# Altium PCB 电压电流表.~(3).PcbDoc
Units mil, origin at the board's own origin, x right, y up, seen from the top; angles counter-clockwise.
Board outline 2295 x 2570 mil, 2 copper layers (Top Layer, Bottom Layer); 25 components, 47 nets, 141 pads, 0 vias.
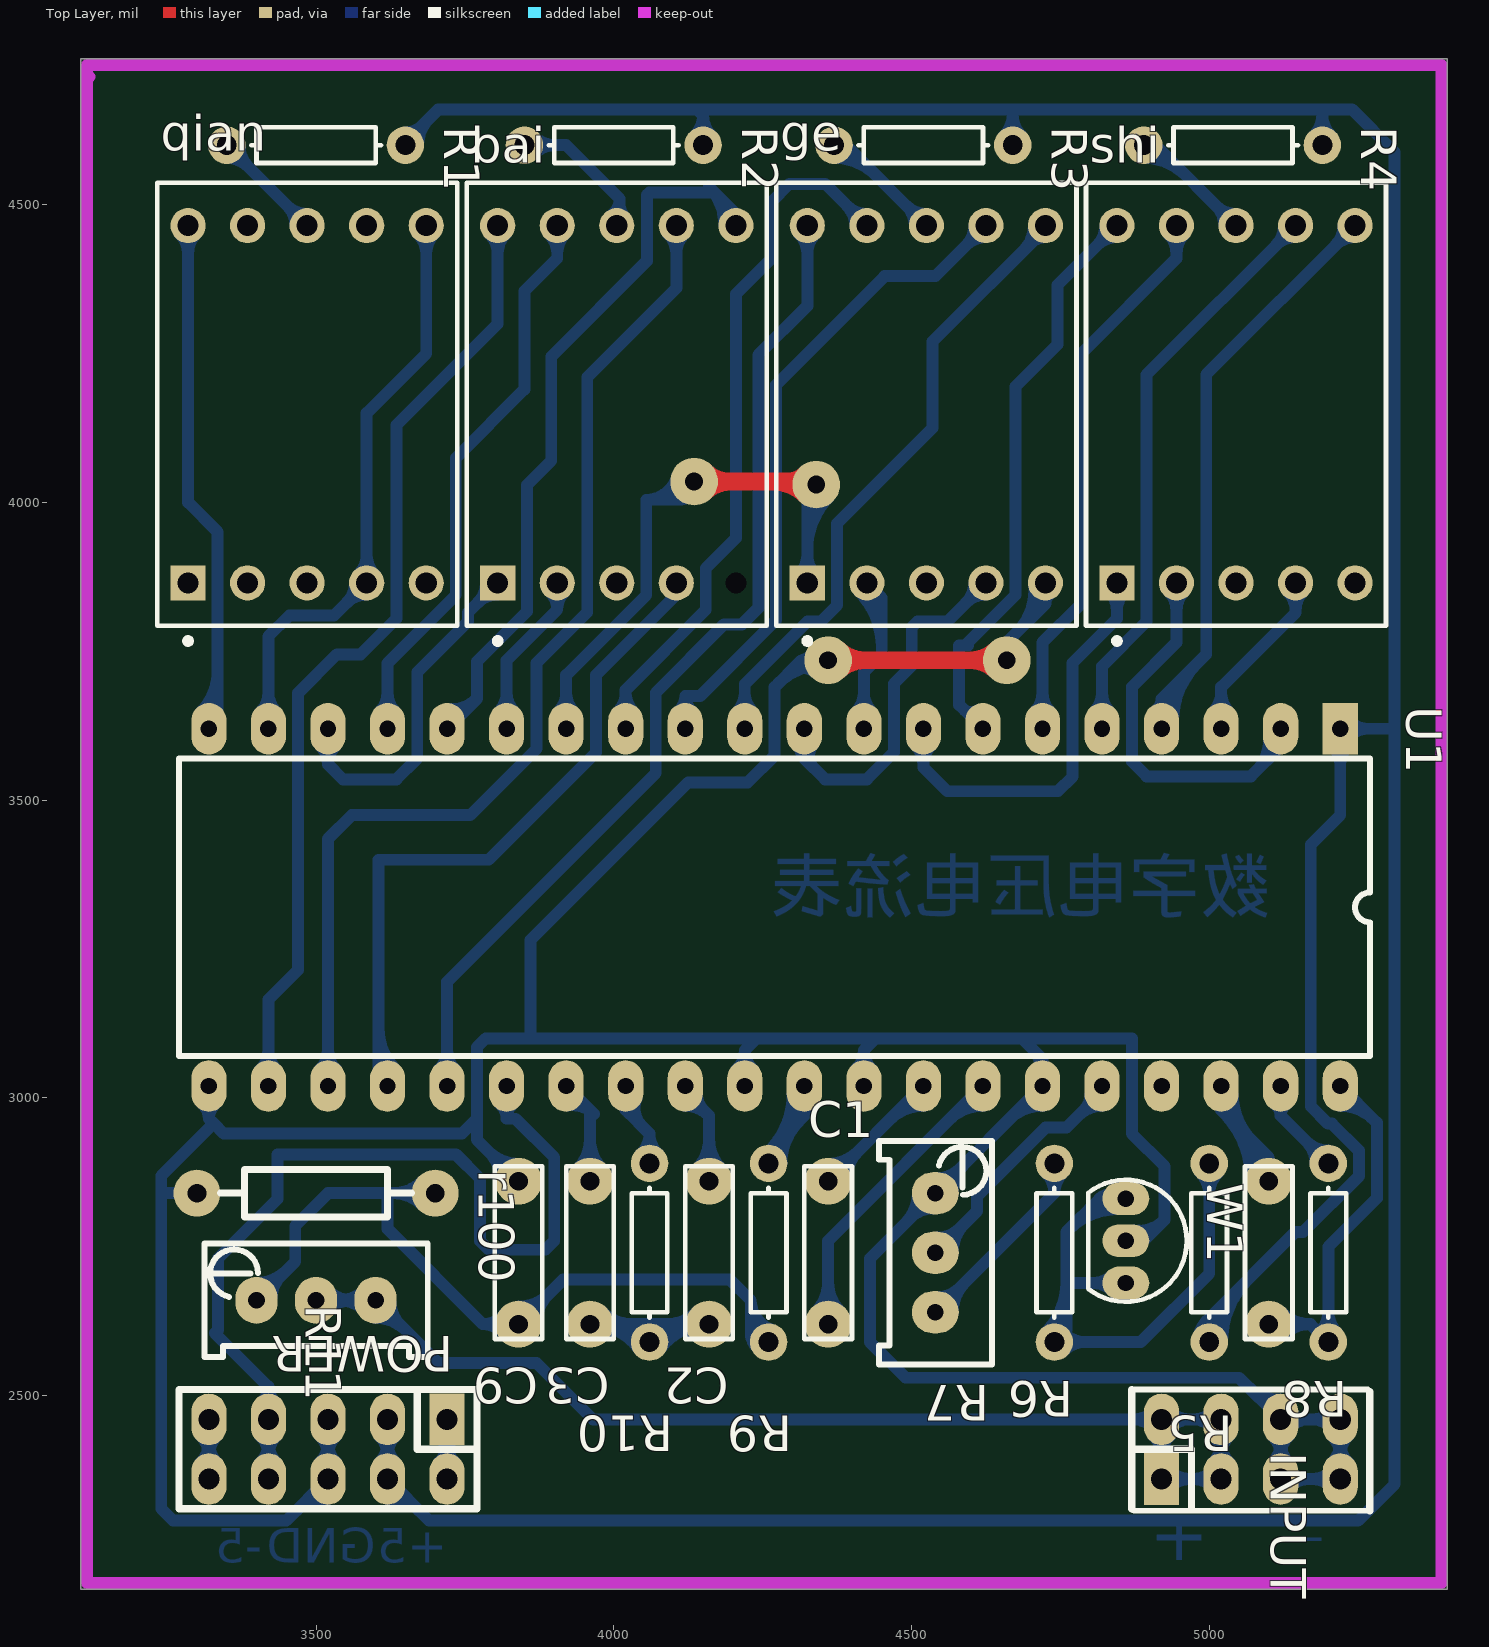
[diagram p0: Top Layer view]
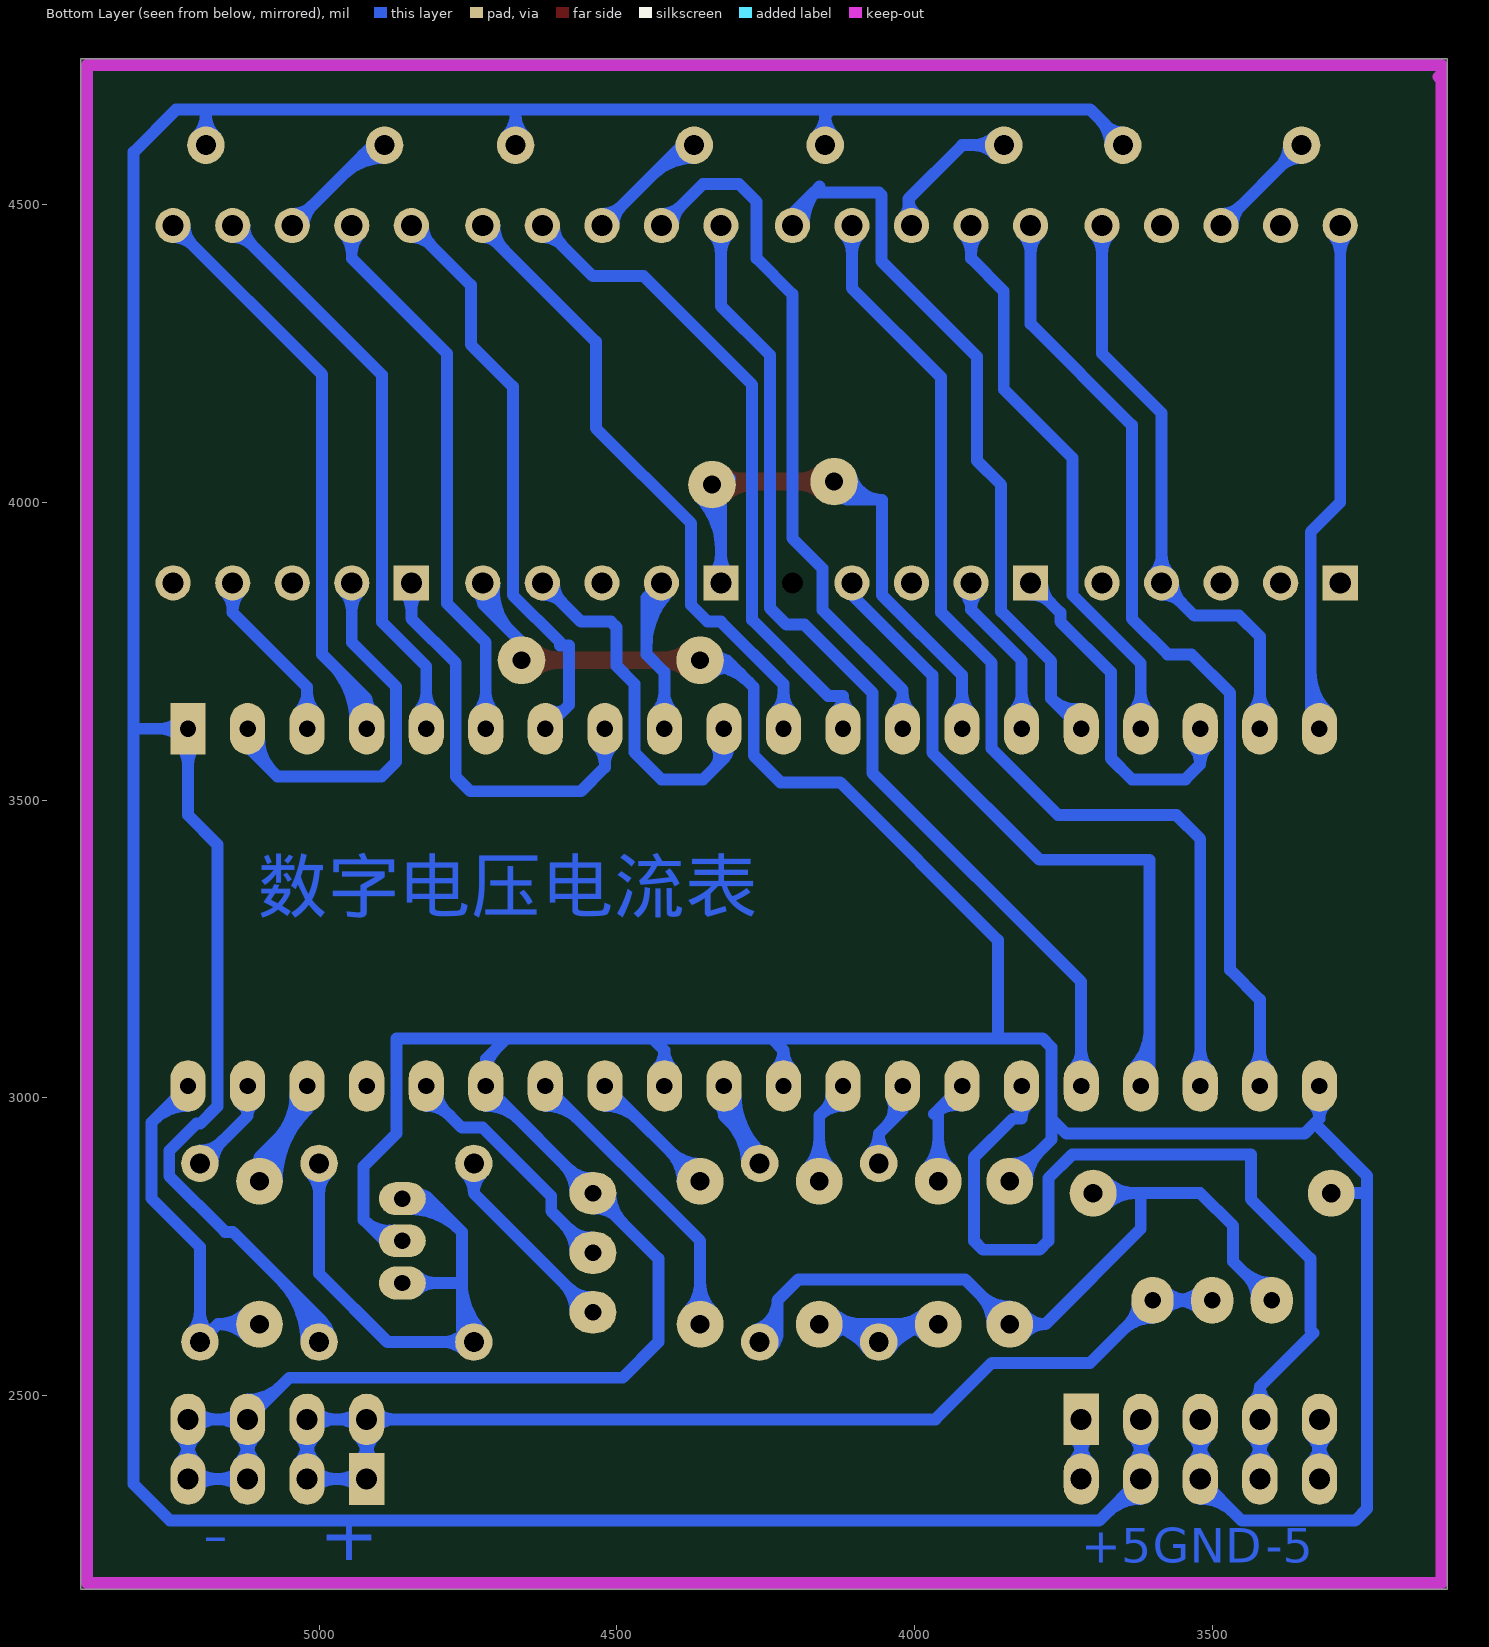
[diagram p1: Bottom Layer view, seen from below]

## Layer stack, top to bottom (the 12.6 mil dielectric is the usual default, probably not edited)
Top Layer: signal copper 1.4
Dielectric: dielectric 12.6, FR-4, Dk 4.8
Bottom Layer: signal copper 1.4

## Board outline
3105,4720 3105,4740 3105,4745 3135,4745 5400,4745 5400,4600 5400,2175 4940,2175 3105,2175 3105,2265

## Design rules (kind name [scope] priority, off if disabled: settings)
Clearance [All] p1: gap=10
HoleSize [All] p1 off: absolutevalues=TRUE maxlimit=100 minlimit=1 maxpercent=80.000 minpercent=20.000
HoleToHoleClearance [All] p1 off: gap=10 allowstackedmicrovias=TRUE
LayerPairs [All] p1 off: enforce=TRUE
MinimumSolderMaskSliver [All] p1 off: minsoldermaskwidth=10
NetAntennae [All] p1 off: netantennaetolerance=0
PolygonConnect [All] p1: connectstyle=Relief reliefconductorwidth=10 reliefentries=4 polygonreliefangle="90 Angle"
RoutingVias [All] p1: holewidth=28 width=50 viastyle="Through Hole" minholewidth=28 minwidth=50 maxholewidth=28 maxwidth=50
SilkToSilkClearance [All] p1 off: silktosilkclearance=10
SilkscreenOverComponentPads [All] p1 off: minsilkscreentomaskgap=10
SolderMaskExpansion [All] p1: expansion=4
TestPointUsage [All] p1: valid=0 allowmultiple=FALSE
Testpoint [All] p1: side=15 testpointundercomponent=TRUE minsize=40 maxsize=100 preferedsize=60 minholesize=0 maxholesize=40 preferedholesize=32 testpointgrid=1 style=1023 order=0123456789
Width [All] p1: maxlimit=30 minlimit=10 preferedwidth=10 toplayer_minwidth=30 toplayer_prefwidth=30 bottomlayer_minwidth=20 bottomlayer_maxwidth=20 bottomlayer_prefwidth=20 minimp=50.000000 maximp=50.000000 favimp=50.000000
17 further rules are at their usual default settings.

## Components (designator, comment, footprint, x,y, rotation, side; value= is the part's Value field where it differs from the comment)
bai "Dpy Blue-CA" LEDDIP-10/C15.24RHD#1 4005,4165 r0 top
C1 "104" CAP2 4360,2740 r90 top
C2 "0.47UF" CAP2 4160,2740 r270 top
C3 "0.22UF" CAP2 3960,2740 r270 top
C9 "103" CAP2 3840,2740 r270 top
ge "Dpy Blue-CA" LEDDIP-10/C15.24RHD#2 4525,4165 r0 top
INPUT "HEADER 4X2" IDC-8 4920,2360 r0 top
POWER "HEADER 5X2" IDC-10 3720,2460 r180 top
qian "Dpy Blue-CA" LEDDIP-10/C15.24RHD#2 3485,4165 r0 top
R1 "1k" AXIAL0.3 3500,4600 r0 top
R2 "1k" AXIAL0.3 4000,4600 r0 top
R3 "1k" AXIAL0.3 4520,4600 r0 top
R4 "1k" AXIAL0.3 5040,4600 r0 top
R5 "1K" AXIAL0.3 5000,2740 r270 top
R6 "10k" AXIAL0.3 4740,2740 r270 top
R7 "RPOT-1" RVR-4 4540,2840 r270 top
R8 "100k" AXIAL0.3 5200,2740 r270 top
R9 "1M" AXIAL0.3 4260,2740 r270 top
R10 "47K" AXIAL0.3 4060,2740 r270 top
R11 "100k" RVR-4 3400,2660 r0 top
r100 "10k" AXIAL0.4 3500,2840 r0 top
shi "Dpy Blue-CA" LEDDIP-10/C15.24RHD#2 5045,4165 r0 top
U1 "ICL7107" PDIP-40 5220,3620 r270 top
W1 "TL431" TO-92 4860,2760 r270 top
? "100pf" CAP2 5100,2740 r270 top

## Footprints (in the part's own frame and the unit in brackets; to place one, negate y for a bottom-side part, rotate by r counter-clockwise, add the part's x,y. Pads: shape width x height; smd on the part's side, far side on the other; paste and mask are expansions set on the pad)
AXIAL0.3 [mm] "Axial Device, Thru-Hole; 2 Leads; 0.3 in Pin Spacing"
  round 1.6 hole 0.85: 1(-3.81,0) 2(3.81,0)
  silkscreen extent -2.77,-0.76 2.77,0.76, body extent -4.1,-0.96 4,1.04, height 2
AXIAL0.4 [mm]
  round 2 hole 0.8: 1(-5.08,0) 2(5.08,0)
  silkscreen extent -4.06,-1.02 4.06,1.02, body extent -5.38,-1.24 5.38,1.27, height 3.25
CAP2 [mm]
  round 2 hole 0.8: 1(-3.048,0) 2(3.048,0)
  silkscreen extent -3.68,-1.02 3.68,1.02, body extent -3.81,-1.02 3.81,1.02, height 8
IDC-8 [mm]
  rect 1.5x2.2 hole 0.9: 1(0,0)
  oval 1.5x2.2 hole 0.9: 2(0,2.54) 3(2.54,0) 4(2.54,2.54) 5(5.08,0) 6(5.08,2.54) 7(7.62,0) 8(7.62,2.54)
  silkscreen extent -1.27,-1.36 8.88,3.81
IDC-10 [mm]
  rect 1.5x2.2 hole 0.9: 1(0,0)
  oval 1.5x2.2 hole 0.9: 2(0,2.54) 3(2.54,0) 4(2.54,2.54) 5(5.08,0) 6(5.08,2.54) 7(7.62,0) 8(7.62,2.54) 9(10.16,0) 10(10.16,2.54)
  silkscreen extent -1.27,-1.27 11.43,3.81
LEDDIP-10/C15.24RHD#1 [mm] "LED, 7-Segment Display, 14.2 mm, RHD; 10 Leads; Row Space 15.24 mm; Pitch 2.54 mm"
  rect 1.5x1.5 hole 0.9: 1(-5.08,-7.62)
  round 1.5 hole 0.9: 2(-2.54,-7.62) 3(0,-7.62) 4(2.54,-7.62) 6(5.08,7.62) 7(2.54,7.62) 8(0,7.62) 9(-2.54,7.62) 10(-5.08,7.62)
  round 0 hole 0.9: 5(5.08,-7.62)
  silkscreen extent -6.4,-10.22 6.4,9.45, body extent -6.4,-9.45 6.4,9.45, height 8.25
LEDDIP-10/C15.24RHD#2 [mm] "LED, 7-Segment Display, 14.2 mm, RHD; 10 Leads; Row Space 15.24 mm; Pitch 2.54 mm"
  rect 1.5x1.5 hole 0.9: 1(-5.08,-7.62)
  round 1.5 hole 0.9: 2(-2.54,-7.62) 3(0,-7.62) 4(2.54,-7.62) 5(5.08,-7.62) 6(5.08,7.62) 7(2.54,7.62) 8(0,7.62) 9(-2.54,7.62) 10(-5.08,7.62)
  silkscreen extent -6.4,-10.22 6.4,9.45, body extent -6.4,-9.45 6.4,9.45, height 8.25
PDIP-40 [mm]
  rect 2.2x1.5 hole 0.7: 1(0,0)
  oval 2.2x1.5 hole 0.7: 2(0,-2.54) 3(0,-5.08) 4(0,-7.62) 5(0,-10.16) 6(0,-12.7) 7(0,-15.24) 8(0,-17.78) 9(0,-20.32) 10(0,-22.86) 11(0,-25.4) 12(0,-27.94) 13(0,-30.48) 14(0,-33.02) 15(0,-35.56) 16(0,-38.1) 17(0,-40.64) 18(0,-43.18) 19(0,-45.72) 20(0,-48.26) 21(15.24,-48.26) 22(15.24,-45.72) 23(15.24,-43.18) 24(15.24,-40.64) 25(15.24,-38.1) 26(15.24,-35.56) 27(15.24,-33.02) 28(15.24,-30.48) 29(15.24,-27.94) 30(15.24,-25.4) 31(15.24,-22.86) 32(15.24,-20.32) 33(15.24,-17.78) 34(15.24,-15.24) 35(15.24,-12.7) 36(15.24,-10.16) 37(15.24,-7.62) 38(15.24,-5.08) 39(15.24,-2.54) 40(15.24,0)
  silkscreen extent 1.27,-49.53 13.97,1.27, body extent 0.15,-50.57 15.44,2.03, height 5.79
RVR-4 [mm] "Top Preset Potentiometer,3296W"
  oval 1.8x2 hole 0.711: 1(0,0) 2(2.54,0) 3(5.08,0)
  silkscreen extent -2.23,-2.41 7.3,2.42, body extent -2.23,-2.41 7.3,2.42, height 11.55
TO-92 [mm] "TO, Flat Index; 3 In-Line, Axial Leads; Body Dia. 4.8mm; Leads 0.48 x 0.5 mm (max)"
  oval 1.4x2 hole 0.7: 1(-1.8,0) 2(0,0) 3(1.8,0)
  silkscreen extent -2.6,-1.6 2.6,2.6, body extent -2.6,-1.66 2.6,2.61, height 8

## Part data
bai ge qian shi: "14.2 mm General Purpose Blue 7-Segment Display: CA, RH DP, Gray Surface"
C1 C2 C3 C9 ?: library part Cap, "Capacitor"
R1 R2 R3 R4 R5 R6 R8 R9 R10 r100: library part RES
R7: "Potentiometer"
R11: library part RPOT-1, "Potentiometer"
U1: "3位半AD转换，可直接驱动LED"

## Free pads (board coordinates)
  round 80 hole 30: 0(4360,3735) 1(4660,3735) 2(4135,4035) 3(4340,4030)

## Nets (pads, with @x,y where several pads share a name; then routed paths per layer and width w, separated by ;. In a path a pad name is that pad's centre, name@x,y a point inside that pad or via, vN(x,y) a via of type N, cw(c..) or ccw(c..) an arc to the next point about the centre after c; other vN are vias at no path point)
-5V: POWER.7 POWER.8 U1.26 | length 1794.2
  Bottom Layer w20: POWER.8@3406.19,2387.59 ccw(c3372.86,2420.92) 3420,2420.92 ccw(c3467.14,2420.92) POWER.8@3433.81,2387.59 ; POWER.7@3406.19,2432.41 cw(c3372.86,2399.08) 3420,2399.08 cw(c3467.14,2399.08) POWER.7@3433.81,2432.41 ; POWER.7@3407.63,2488.89 ccw(c3386.26,2515) 3420,2515 ; POWER.8 POWER.7 3420,2515 ; POWER.7@3432.37,2488.89 cw(c3453.74,2515) 3420,2515 ; U1.26@3807.63,2991.11 cw(c3786.26,2965) 3820,2965 ; U1.26 3820,2965 ; U1.26@3832.37,2991.11 ccw(c3853.74,2965) 3820,2965 ; 3420,2515 3330,2605 3335,2610 3335,2730 3435,2830 3435,2905 3735,2905 3775,2865 3775,2760 3790,2745 3885,2745 3900,2760 3900,2900 3835,2965 3820,2965
BAI1: bai.7 U1.23 | length 1951.9
  Bottom Layer w20: U1.23@3506.19,3047.59 ccw(c3472.86,3080.92) 3520,3080.92 ccw(c3567.14,3080.92) U1.23@3533.81,3047.59 ; U1.23 3520,3435 3560,3475 3758.82,3475 3870.47,3586.65 3870.47,3730.47 3955.47,3815.47 3955.47,4210.47 4105,4360 bai.7 ; bai.7@4091.19,4451.19 cw(c4057.86,4417.86) 4105,4417.86 cw(c4152.14,4417.86) bai.7@4118.81,4451.19
BAI2: bai.6 U1.16 | length 1389.5
  Bottom Layer w20: U1.16 3770.47,3670.47 ; U1.16@3721.98,3653.21 ccw(c3728.05,3712.89) 3770.47,3670.47 ; 4159.53,4530.47 cw(c4096.82,4467.76) bai.6@4185.48,4465.5 ; 4192.48,4497.52 cw(c4161.08,4466.12) bai.6@4205.47,4464.99 ; bai.6@4210,4460 4210,4480 4169.53,4520.47 4059.53,4520.47 4055.47,4516.42 4055.47,4405.47 3895,4245 3895,4070 3854.53,4029.53 3854.53,3817.1 3770.47,3733.05 3770.47,3670.47
BAI3: bai.4 U1.24 | length 1283.3
  Bottom Layer w20: 3605,3068.85 ccw(c3655.07,3068.85) U1.24@3619.67,3033.45 ; 3605,3117.14 ccw(c3703.36,3117.14) U1.24@3633.81,3047.59 ; U1.24 3605,3035 3605,3400 3790,3400 3970,3580 3970,3710 4105,3845 bai.4
BAI4: bai.2 U1.15 | length 423.2
  Bottom Layer w20: U1.15@3806.19,3647.59 ccw(c3772.86,3680.92) 3820,3680.92 ccw(c3867.14,3680.92) U1.15@3833.81,3647.59 ; U1.15 3820,3735 3905,3820 ; bai.2@3891.66,3850.74 cw(c3862.92,3820) 3905,3820 ; bai.2 3905,3820 ; bai.2@3918.34,3850.74 ccw(c3947.08,3820) 3905,3820
BAI5: bai.1 U1.18 | length 731.7
  Bottom Layer w20: U1.18@3506.39,3592.22 cw(c3475.07,3560) 3520,3560 ; U1.18 3520,3560 ; U1.18@3533.61,3592.22 ccw(c3564.93,3560) 3520,3560 ; bai.1@3785.47,3865 cw(c3738.33,3865) 3771.66,3831.66 cw(c3805,3798.33) bai.1@3805,3845.47 ; bai.1 3755,3815 3755,3800 3670,3715 3670,3570 3635,3535 3545,3535 3520,3560
BAI6: bai.9 U1.17 | length 1111.2
  Bottom Layer w20: U1.17@3606.19,3647.59 ccw(c3572.86,3680.92) 3620,3680.92 ccw(c3667.14,3680.92) U1.17@3633.81,3647.59 ; U1.17 3620,3729.96 3734.53,3844.49 3734.53,4074.53 3850,4190 3850,4355 3905,4410 bai.9 ; bai.9@3891.19,4451.19 cw(c3857.86,4417.86) 3905,4417.86 cw(c3952.14,4417.86) bai.9@3918.81,4451.19
BAI7: bai.10 U1.22 | length 1776
  Bottom Layer w20: U1.22@3406.19,3047.59 ccw(c3372.86,3080.92) 3420,3080.92 ccw(c3467.14,3080.92) U1.22@3433.81,3047.59 ; U1.22 3420,3165 3470,3215 3470,3680 3535,3745 3575,3745 3635,3805 3635,4130 3805,4300 bai.10 ; bai.10@3791.19,4451.19 cw(c3757.86,4417.86) 3805,4417.86 cw(c3852.14,4417.86) bai.10@3818.81,4451.19
FU: qian.10 U1.20 | length 1101.4
  Bottom Layer w20: qian.10@3271.19,4451.19 cw(c3237.86,4417.86) 3285,4417.86 cw(c3332.14,4417.86) qian.10@3298.81,4451.19 ; qian.10 3285,4000 3334.53,3950.47 3334.53,3649.53 3305,3620 U1.20 U1.20@3334.53,3634.53 ; U1.20@3306.19,3647.59 ccw(c3237.78,3716) 3334.53,3716 ; U1.20@3320.33,3633.45 ccw(c3286.07,3667.71) 3334.53,3667.71
GE1: shi.7 U1.5 | length 1127.7
  Bottom Layer w20: U1.5@4806.19,3647.59 ccw(c4772.86,3680.92) 4820,3680.92 ccw(c4867.14,3680.92) U1.5@4833.81,3647.59 ; U1.5 4820,3725 4894.53,3799.53 4894.53,4214.53 shi.7 ; shi.7@5125.47,4465 cw(c5078.33,4465) 5111.66,4431.66 cw(c5145,4398.33) shi.7@5145,4445.47
GE2: shi.6 U1.4 | length 1309.3
  Bottom Layer w20: U1.4@4909.27,3650.09 ccw(c4896.18,3670) 4920,3670 ; U1.4@4919.53,3633.78 cw(c5005.83,3633.78) 4944.81,3694.81 ; U1.4@4920,3655 U1.4 4920,3670 ; U1.4@4930.73,3650.09 cw(c4943.82,3670) 4920,3670 ; U1.4@4939.53,3633.78 cw(c5074.12,3633.78) 4978.95,3728.95 ; shi.6@5225.47,4465 cw(c5178.33,4465) 5211.66,4431.66 cw(c5245,4398.33) shi.6@5245,4445.47 ; shi.6 4995,4215 4995,3745 4920,3670
GE3: shi.4 U1.3 | length 489.9
  Bottom Layer w20: U1.3@5006.19,3647.59 ccw(c4972.86,3680.92) 5020,3680.92 ccw(c5067.14,3680.92) U1.3@5033.81,3647.59 ; 5020,3665 U1.3 5020,3690 5145,3815 shi.4 ; shi.4@5131.19,3851.19 cw(c5097.86,3817.86) 5145,3817.86 cw(c5192.14,3817.86) shi.4@5158.81,3851.19
GE4: shi.2 U1.2 | length 779.1
  Bottom Layer w20: shi.2@4931.19,3851.19 cw(c4897.86,3817.86) 4945,3817.86 cw(c4992.14,3817.86) shi.2@4958.81,3851.19 ; shi.2 4945,3765 4870.47,3690.47 4870.47,3564.53 4895,3540 5070,3540 5120,3590 U1.2 ; 5078.11,3548.11 ccw(c5023.94,3602.29) U1.2@5100.49,3605.42
GE5: shi.1 U1.8 | length 846.6
  Bottom Layer w20: U1.8@4506.19,3592.41 cw(c4472.86,3559.08) 4520,3559.08 cw(c4567.14,3559.08) U1.8@4533.81,3592.41 ; U1.8 4520,3555 4560,3515 4745.94,3515 4770.47,3539.53 4770.47,3730.47 4845,3805 shi.1 ; shi.1@4831.19,3851.19 cw(c4797.86,3817.86) 4845,3817.86 cw(c4892.14,3817.86) shi.1@4858.81,3851.19
GE6: shi.9 U1.6 | length 1086.3
  Bottom Layer w20: U1.6@4706.19,3647.59 ccw(c4672.86,3680.92) 4720,3680.92 ccw(c4767.14,3680.92) U1.6@4733.81,3647.59 ; U1.6 4720,3765 4785,3830 4785,4250 4945,4410 shi.9 ; shi.9@4931.19,4451.19 cw(c4897.86,4417.86) 4945,4417.86 cw(c4992.14,4417.86) shi.9@4958.81,4451.19
GE7: shi.10 U1.7 | length 1079
  Bottom Layer w20: 4586.89,3653.11 ccw(c4600.04,3666.26) U1.7@4609.78,3650.42 ; U1.7 4580,3660 4580,3760 4595,3760 4595,3764.96 4674.53,3844.49 4674.53,4194.53 4745,4265 4745,4365 shi.10 ; shi.10@4825.47,4465 cw(c4778.33,4465) 4811.66,4431.66 cw(c4845,4398.33) shi.10@4845,4445.47
GND: C9.1 ge.5 INPUT.5 INPUT.6 INPUT.7 INPUT.8 pad.0 pad.1 POWER.5 POWER.6 R7.1 r100.1 U1.21 U1.30 U1.32 U1.35 W1.2 | length 9034.4
  Top Layer w30: pad.0 pad.1 ; pad.0@4377.68,3717.32 cw(c4420.36,3674.64) 4420.36,3735 cw(c4420.36,3795.36) pad.0@4377.68,3752.68 ; pad.1@4642.32,3717.32 ccw(c4599.64,3674.64) 4599.64,3735 ccw(c4599.64,3795.36) pad.1@4642.32,3752.68
  Bottom Layer w20: r100.1 3240,2840 ; U1.21@3307.63,2991.11 cw(c3286.26,2965) 3320,2965 ; U1.21 3320,2965 ; U1.21@3332.37,2991.11 ccw(c3353.74,2965) 3320,2965 ; 3463.14,2303.14 cw(c3520,2246.28) POWER.6@3520,2326.69 ; POWER.6@3506.19,2387.59 ccw(c3472.86,2420.92) 3520,2420.92 ccw(c3567.14,2420.92) POWER.6@3533.81,2387.59 ; POWER.5@3506.19,2432.41 cw(c3472.86,2399.08) 3520,2399.08 cw(c3567.14,2399.08) POWER.5@3533.81,2432.41 ; POWER.5 POWER.6 3450,2290 3260,2290 3240,2310 3240,2840 ; C9.1@3810.63,2860 ccw(c3739.72,2860) 3789.86,2910.14 ccw(c3840,2960.28) C9.1@3840,2889.37 ; C9.1 3770,2930 3770,2965 ; U1.30@4206.39,3047.78 ccw(c4175.07,3080) 4220,3080 ; U1.30 4220,3080 ; U1.30@4233.61,3047.78 cw(c4264.93,3080) 4220,3080 ; 4276.62,3696.62 cw(c4347,3626.24) pad.0@4358.81,3725.07 ; 4292.5,3712.5 cw(c4316.31,3688.7) pad.0@4339.41,3713.18 ; 4305.74,3725.74 cw(c4353.22,3678.25) pad.0@4361.19,3744.93 ; 4307.06,3727.06 cw(c4330.44,3703.68) pad.0@4353.14,3727.73 ; pad.0@4332.31,3723.46 ccw(c4315,3716.25) 4315,3735 ; pad.0@4332.31,3746.54 cw(c4315,3753.75) 4315,3735 ; pad.0 4315,3735 ; U1.32@4406.39,3047.78 ccw(c4375.07,3080) 4420,3080 ; U1.32 4420,3080 ; U1.32@4433.61,3047.78 cw(c4464.93,3080) 4420,3080 ; 4489.86,2789.86 ccw(c4439.72,2840) R7.1@4510.63,2840 ; 4499.37,2799.37 cw(c4536.06,2762.67) R7.1@4536.06,2814.57 ; R7.1@4543.94,2865.43 ccw(c4543.94,2917.33) 4580.63,2880.63 ; R7.1@4569.37,2840 cw(c4640.28,2840) 4590.14,2890.14 ; pad.1 4660,3765 4725,3830 ; 4663.14,2963.14 cw(c4720,2906.28) U1.35@4720,2986.69 ; 4677.5,3782.5 ccw(c4608.19,3851.82) ge.5@4705.6,3862.81 ; 4701.23,3083.77 cw(c4654.55,3037.1) U1.35@4720.47,3033.76 ; 4706.86,3811.86 ccw(c4660.95,3857.77) ge.5@4725.47,3865.05 ; ge.5@4714.74,3848.38 cw(c4703.4,3830) 4725,3830 ; ge.5@4725,3850 ge.5 4725,3830 ; ge.5@4735.26,3848.38 ccw(c4746.6,3830) 4725,3830 ; W1.2 4890,2760 4925,2795 ; W1.2@4873.95,2777.43 ccw(c4881.47,2838.53) 4925,2795 ; 5063.14,2516.86 ccw(c5120,2573.72) INPUT.6@5120,2493.31 ; INPUT.5@5106.19,2387.59 ccw(c5072.86,2420.92) 5120,2420.92 ccw(c5167.14,2420.92) INPUT.5@5133.81,2387.59 ; INPUT.6@5106.19,2432.41 cw(c5072.86,2399.08) 5120,2399.08 cw(c5167.14,2399.08) INPUT.6@5133.81,2432.41 ; INPUT.5 INPUT.7 INPUT.8 INPUT.6 ; INPUT.5@5120,2370 INPUT.6 ; INPUT.5@5133.81,2346.19 cw(c5167.14,2312.86) 5167.14,2360 cw(c5167.14,2407.14) INPUT.5@5133.81,2373.81 ; INPUT.6@5133.81,2446.19 cw(c5167.14,2412.86) 5167.14,2460 cw(c5167.14,2507.14) INPUT.6@5133.81,2473.81 ; INPUT.7@5206.19,2346.19 ccw(c5172.86,2312.86) 5172.86,2360 ccw(c5172.86,2407.14) INPUT.7@5206.19,2373.81 ; INPUT.7@5206.19,2387.59 ccw(c5172.86,2420.92) 5220,2420.92 ccw(c5267.14,2420.92) INPUT.7@5233.81,2387.59 ; INPUT.8@5206.19,2432.41 cw(c5172.86,2399.08) 5220,2399.08 cw(c5267.14,2399.08) INPUT.8@5233.81,2432.41 ; INPUT.8@5206.19,2446.19 ccw(c5172.86,2412.86) 5172.86,2460 ccw(c5172.86,2507.14) INPUT.8@5206.19,2473.81 ; 3240,2840 3240,2869.28 3327.86,2957.14 ; 3320,2965 3327.86,2957.14 ; 3327.86,2957.14 3345,2940 3745,2940 3770,2965 ; 3770,2965 3770,3085 3785,3100 3860,3100 ; 3860,3100 3860,3265 4125,3530 4225,3530 4270,3575 4270,3690 4315,3735 ; 3860,3100 4240,3100 ; 4220,3080 4240,3100 ; 4240,3100 4440,3100 ; 4420,3080 4440,3100 ; 4440,3100 4685,3100 ; 4685,3100 4870,3100 4870,2940 4925,2885 4925,2795 ; 4685,3100 4720,3065 U1.35 R7.1 4430,2730 4430,2590 4490,2530 5050,2530 INPUT.6
IN+: C9.2 R9.2 R11.1 r100.2 | length 1868.9
  Bottom Layer w20: R11.1 3465,2725 3465,2785 3520,2840 3620,2840 ; R11.1@3400,2689.37 ccw(c3400,2760.28) 3450.14,2710.14 ; R11.1@3425.43,2663.94 cw(c3477.33,2663.94) 3440.63,2700.63 ; r100.2@3679.23,2819.23 ccw(c3629.09,2769.09) 3629.09,2840 ccw(c3629.09,2910.91) r100.2@3679.23,2860.77 ; r100.2 3620,2840 ; C9.2@3816.8,2601.99 ccw(c3780,2573.4) 3780,2620 ; C9.2@3816.8,2638.01 cw(c3780,2666.6) 3780,2620 ; C9.2@3840,2649.37 ccw(c3840,2720.28) 3890.14,2670.14 ccw(c3940.28,2620) C9.2@3869.37,2620 ; 4230,2605.63 ccw(c4264.87,2605.63) R9.2@4254.49,2572.33 ; 4230,2632.81 ccw(c4273.35,2632.81) R9.2@4260.45,2591.43 ; R9.2@4240,2590 4230,2600 ; R9.2 4250,2600 4230,2600 ; R9.2@4266.4,2610.52 cw(c4281.83,2660) 4230,2660 ; 3620,2840 3620,2780 3780,2620 ; 3780,2620 C9.2 3915,2695 4195,2695 4230,2660 ; 4230,2600 4230,2660
Net_1: ?.1 U1.38 | length 609.5
  Bottom Layer w20: U1.38@5019.53,3006.22 ccw(c5081.69,3006.22) 5037.73,2962.27 ; U1.38 5020,2980 5100,2900 ?.1 ; U1.38@5021.58,2978.42 cw(c4903.16,2860) ?.1@5070.63,2860 ; U1.38@5039.53,3006.22 ccw(c5149.97,3006.22) 5071.88,2928.12 ; 5055.72,2944.28 cw(c4971.44,2860) ?.1@5090.63,2860 ; 5089.86,2910.14 cw(c5039.72,2860) ?.1@5110.63,2860
Net_2: ?.2 R8.2 U1.40 | length 855.5
  Bottom Layer w20: ?.2 5170,2620 ; ?.2@5120.96,2599.42 cw(c5170,2551.27) 5170,2620 ; ?.2@5120.96,2640.58 ccw(c5170,2688.73) 5170,2620 ; R8.2@5184.8,2605.2 ccw(c5148.1,2641.9) 5200,2641.9 ccw(c5251.9,2641.9) R8.2@5215.2,2605.2 ; U1.40@5220,2986.69 cw(c5220,2906.28) 5276.86,2963.14 ; U1.40 5281.5,2958.5 5281.5,2831.5 5200,2750 R8.2 5170,2620
Netbai_8: bai.8 R2.1 | length 386.4
  Bottom Layer w20: R2.1 3920,4600 4010,4510 ; R2.1@3865.2,4584.8 cw(c3901.9,4548.1) 3901.9,4600 cw(c3901.9,4651.9) R2.1@3865.2,4615.2 ; bai.8@3994.42,4481.41 ccw(c3975.99,4510) 4010,4510 ; bai.8@4010,4460 4010,4510 ; 4010,4500.07 ccw(c4040.07,4500.07) bai.8@4018.81,4478.81
NetC1_1: C1.1 U1.34 | length 682.2
  Bottom Layer w20: C1.1@4339.23,2640.77 ccw(c4289.09,2690.91) 4360,2690.91 ccw(c4430.91,2690.91) C1.1@4380.77,2640.77 ; C1.1 4360,2760 U1.34 ; 4563.14,2963.14 cw(c4620,2906.28) U1.34@4620,2986.69
NetC1_2: C1.2 U1.33 | length 400.8
  Bottom Layer w20: C1.2 U1.33 ; C1.2@4360,2889.37 ccw(c4360,2960.28) 4410.14,2910.14 ccw(c4460.28,2860) C1.2@4389.37,2860 ; 4463.14,2963.14 cw(c4520,2906.28) U1.33@4520,2986.69
NetC2_1: C2.1 U1.29 | length 362
  Bottom Layer w20: U1.29@4120,2986.69 cw(c4120,2930.42) 4159.79,2970.21 ; U1.29 4120,3010 4160,2970 C2.1 ; C2.1@4139.23,2880.77 ccw(c4089.09,2930.91) 4160,2930.91 ccw(c4230.91,2930.91) C2.1@4180.77,2880.77 ; U1.29@4139.53,3006.22 ccw(c4177.55,3006.22) 4150.66,2979.34
NetC2_2: C2.2 C3.2 R10.2 | length 873
  Bottom Layer w20: C3.2@3980.77,2599.23 cw(c4030.91,2549.09) 4030.91,2620 cw(c4030.91,2690.91) C3.2@3980.77,2640.77 ; C3.2@3998.84,2620 cw(c3998.84,2546.37) R10.2@4058.78,2589.13 ; 4037.68,2620 cw(c4037.68,2574.07) R10.2@4075.06,2600.75 ; R10.2@4042.5,2577.52 ccw(c3960,2518.66) C3.2 R10.2@4060,2620 ; R10.2@4044.94,2600.75 cw(c4082.32,2574.07) 4082.32,2620 ; R10.2 R10.2@4060,2620 ; R10.2@4061.22,2589.13 cw(c4121.16,2546.37) C2.2@4121.16,2620 ; R10.2@4077.5,2577.52 cw(c4160,2518.66) C2.2 R10.2@4060,2620 ; C2.2@4139.23,2599.23 ccw(c4089.09,2549.09) 4089.09,2620 ccw(c4089.09,2690.91) C2.2@4139.23,2640.77
NetC3_1: C3.1 U1.27 | length 335.5
  Bottom Layer w20: U1.27 3960,2980 C3.1 ; U1.27@3923.3,2986.97 cw(c3931.7,2937.92) 3966.89,2973.11 ; C3.1@3939.23,2880.77 ccw(c3889.09,2930.91) 3960,2930.91 ccw(c4030.91,2930.91) C3.1@3980.77,2880.77
Netge_8: ge.8 R3.1 | length 404.4
  Bottom Layer w20: R3.1@4370,4578.5 cw(c4370,4478.32) 4440.84,4549.16 ; R3.1@4370,4598.5 cw(c4370,4546.61) 4406.7,4583.3 ; R3.1 4390,4600 ge.8 ; ge.8@4505.47,4465 ccw(c4458.33,4465) 4491.66,4498.34 ccw(c4525,4531.67) ge.8@4525,4484.53
NetINPUT_1: INPUT.1 INPUT.2 INPUT.3 INPUT.4 R11.2 R11.3 | length 2858.7
  Bottom Layer w20: R11.2 R11.3 3705,2555 3870,2555 3965,2460 INPUT.2 ; R11.2@3517.98,2642.02 cw(c3561.4,2598.6) 3561.4,2660 cw(c3561.4,2721.4) R11.2@3517.98,2677.98 ; R11.3@3582.02,2642.02 ccw(c3538.6,2598.6) 3538.6,2660 ccw(c3538.6,2721.4) R11.3@3582.02,2677.98 ; R11.3@3600,2630.63 cw(c3600,2559.72) 3650.14,2609.86 ; R11.3@3625.43,2656.06 ccw(c3677.33,2656.06) 3640.63,2619.37 ; INPUT.1@4906.19,2387.59 ccw(c4872.86,2420.92) 4920,2420.92 ccw(c4967.14,2420.92) INPUT.1@4933.81,2387.59 ; INPUT.2@4906.19,2432.41 cw(c4872.86,2399.08) 4920,2399.08 cw(c4967.14,2399.08) INPUT.2@4933.81,2432.41 ; INPUT.2@4906.19,2446.19 ccw(c4872.86,2412.86) 4872.86,2460 ccw(c4872.86,2507.14) INPUT.2@4906.19,2473.81 ; INPUT.1@4933.81,2346.19 cw(c4967.14,2312.86) 4967.14,2360 cw(c4967.14,2407.14) INPUT.1@4933.81,2373.81 ; INPUT.2@4933.81,2446.19 cw(c4967.14,2412.86) 4967.14,2460 cw(c4967.14,2507.14) INPUT.2@4933.81,2473.81 ; INPUT.3@5006.19,2346.19 ccw(c4972.86,2312.86) 4972.86,2360 ccw(c4972.86,2407.14) INPUT.3@5006.19,2373.81 ; INPUT.3@5006.19,2387.59 ccw(c4972.86,2420.92) 5020,2420.92 ccw(c5067.14,2420.92) INPUT.3@5033.81,2387.59 ; INPUT.4@5006.19,2432.41 cw(c4972.86,2399.08) 5020,2399.08 cw(c5067.14,2399.08) INPUT.4@5033.81,2432.41 ; INPUT.4@5006.19,2446.19 ccw(c4972.86,2412.86) 4972.86,2460 ccw(c4972.86,2507.14) INPUT.4@5006.19,2473.81 ; INPUT.2 INPUT.4 INPUT.3 INPUT.1 INPUT.2
NetPOWER_1: POWER.1 POWER.2 | length 248.1
  Bottom Layer w20: POWER.2@3706.19,2387.59 ccw(c3672.86,2420.92) 3720,2420.92 ccw(c3767.14,2420.92) POWER.2@3733.81,2387.59 ; POWER.1@3706.19,2432.41 cw(c3672.86,2399.08) 3720,2399.08 cw(c3767.14,2399.08) POWER.1@3733.81,2432.41 ; POWER.2 POWER.1
NetPOWER_9: POWER.9 POWER.10 | length 248.1
  Bottom Layer w20: POWER.10@3306.19,2387.59 ccw(c3272.86,2420.92) 3320,2420.92 ccw(c3367.14,2420.92) POWER.10@3333.81,2387.59 ; POWER.9@3306.19,2432.41 cw(c3272.86,2399.08) 3320,2399.08 cw(c3367.14,2399.08) POWER.9@3333.81,2432.41 ; POWER.10 POWER.9
Netqian_8: qian.8 R1.1 | length 346.5
  Bottom Layer w20: R1.1@3350,4578.5 cw(c3350,4526.61) 3386.7,4563.3 cw(c3423.39,4600) R1.1@3371.5,4600 ; R1.1 qian.8 ; qian.8@3465.47,4465 ccw(c3418.33,4465) 3451.66,4498.34 ccw(c3485,4531.67) qian.8@3485,4484.53
NetR4_1: R4.1 shi.8 | length 404.4
  Bottom Layer w20: R4.1@4890,4578.5 cw(c4890,4478.32) 4960.84,4549.16 ; R4.1@4890,4598.5 cw(c4890,4546.61) 4926.7,4583.3 ; R4.1 4910,4600 shi.8 ; shi.8@5025.47,4465 ccw(c4978.33,4465) 5011.66,4498.34 ccw(c5045,4531.67) shi.8@5045,4484.53
NetR5_1: R5.1 R6.2 W1.1 W1.3 | length 1561.1
  Bottom Layer w20: R6.2@4724.82,2605.22 ccw(c4640.27,2689.99) 4760,2689.99 ; R6.2@4738.94,2591.06 ccw(c4688.34,2641.8) 4760,2641.8 ; R6.2@4755.2,2574.8 cw(c4791.9,2538.1) 4791.9,2590 cw(c4791.9,2641.9) R6.2@4755.2,2605.2 ; 4763.04,2778.04 cw(c4848.19,2692.88) W1.1@4848.19,2813.31 ; 4797.18,2812.18 cw(c4848.19,2761.17) W1.1@4848.19,2833.31 ; 4799.71,2814.71 cw(c4819.86,2794.55) W1.1@4837.39,2817.02 ; 4815.7,2830.7 cw(c4833.88,2812.52) W1.1@4849.69,2832.79 ; W1.1@4833.46,2821.31 ccw(c4815.87,2809.9) 4815.87,2830.87 ; W1.1@4833.46,2840.42 cw(c4815.87,2851.83) 4815.87,2830.87 ; W1.3@4835.77,2676.72 ccw(c4805.8,2646.74) 4805.8,2689.13 ccw(c4805.8,2731.53) W1.3@4835.77,2701.55 ; W1.3 4760.87,2689.13 4760,2690 ; W1.1 4815.87,2830.87 ; R5.1@4984.8,2874.8 cw(c4948.1,2838.1) 5000,2838.1 cw(c5051.9,2838.1) R5.1@5015.2,2874.8 ; R5.1 5000,2705 4885,2590 R6.2 4760,2610 4760,2690 ; 4760,2690 4760,2775 4815.87,2830.87
NetR6_1: R6.1 R7.3 | length 506.3
  Bottom Layer w20: R7.3 4740,2840 ; R7.3@4543.94,2665.43 ccw(c4543.94,2717.33) 4580.63,2680.63 ; R7.3@4569.37,2640 cw(c4640.28,2640) 4590.14,2690.14 ; R6.1@4725.21,2874.4 cw(c4692.6,2840) 4740,2840 ; R6.1 4740,2840 ; R6.1@4754.79,2874.4 ccw(c4787.4,2840) 4740,2840
NetR7_2: R7.2 U1.36 | length 587
  Bottom Layer w20: R7.2 4610,2810 4610,2835 4725,2950 4760,2950 4820,3010 U1.36 ; R7.2@4543.94,2765.43 ccw(c4543.94,2817.33) 4580.63,2780.63 ; R7.2@4569.37,2740 cw(c4640.28,2740) 4590.14,2790.14 ; 4780.21,2970.21 cw(c4820,2930.42) U1.36@4820,2986.69 ; 4789.34,2979.34 ccw(c4762.45,3006.22) U1.36@4800.47,3006.22
NetR8_1: R8.1 U1.39 | length 338.9
  Bottom Layer w20: U1.39 5120,2970 ; R8.1@5178.5,2890 ccw(c5126.61,2890) 5163.3,2926.7 ccw(c5200,2963.39) R8.1@5200,2911.5 ; R8.1 5120,2970 ; 5120,2970 ccw(c5096.18,2970) 5109.27,2989.91 cw(c5096.18,2970) 5120,2970 ; 5120,2970 cw(c5143.82,2970) 5130.73,2989.91 ccw(c5143.82,2970) 5120,2970
NetR9_1: R9.1 U1.31 | length 503.2
  Bottom Layer w20: R9.1@4240,2890 4320,2970 ; R9.1@4261.05,2911.05 ccw(c4165.88,3006.22) U1.31@4300.47,3006.22 ; R9.1@4261.5,2890 cw(c4313.39,2890) 4276.7,2926.7 ; R9.1@4281.5,2890 cw(c4381.68,2890) 4310.84,2960.84 ; 4295.19,2945.19 ccw(c4234.17,3006.22) U1.31@4320.47,3006.22 ; U1.31@4309.27,2989.91 cw(c4296.18,2970) 4320,2970 ; U1.31 4320,2970 ; U1.31@4330.73,2989.91 ccw(c4343.82,2970) 4320,2970
NetR10_1: R10.1 U1.28 | length 307.6
  Bottom Layer w20: U1.28@4019.56,3006.4 ccw(c4046.7,2994.95) 4025.87,2974.13 ; U1.28 4020,2980 4060,2940 ; U1.28@4037.99,2998.63 ccw(c4076.26,2982.48) 4046.89,2953.11 ; R10.1@4045.21,2905.6 ccw(c4012.6,2940) 4060,2940 ; R10.1 4060,2940 ; R10.1@4074.79,2905.6 cw(c4107.4,2940) 4060,2940
QIAN: qian.4 qian.6 U1.19 | length 1294.9
  Bottom Layer w20: U1.19@3406.19,3647.59 ccw(c3372.86,3680.92) 3420,3680.92 ccw(c3467.14,3680.92) U1.19@3433.81,3647.59 ; U1.19 3420,3775 3455,3810 3530,3810 qian.4 3585,4150 3685,4250 qian.6 ; qian.4@3565.47,3865 cw(c3518.33,3865) 3551.66,3831.66 cw(c3585,3798.33) qian.4@3585,3845.47 ; qian.4@3571.19,3878.81 ccw(c3537.86,3912.14) 3585,3912.14 ccw(c3632.14,3912.14) qian.4@3598.81,3878.81 ; qian.6@3671.19,4451.19 cw(c3637.86,4417.86) 3685,4417.86 cw(c3732.14,4417.86) qian.6@3698.81,4451.19
SHI1: ge.7 U1.12 | length 1252.4
  Bottom Layer w20: U1.12@4107.63,3648.89 ccw(c4086.26,3675) 4120,3675 ; U1.12 4120,3675 ; U1.12@4132.37,3648.89 cw(c4153.74,3675) 4120,3675 ; ge.7@4605.47,4465 cw(c4558.33,4465) 4591.66,4431.66 cw(c4625,4398.33) ge.7@4625,4445.47 ; ge.7 4540,4380 4455,4380 4272.72,4197.72 4272.72,3802.72 4145,3675 4120,3675
SHI2: ge.6 U1.11 | length 1253
  Bottom Layer w20: U1.11@4206.19,3647.59 ccw(c4172.86,3680.92) 4220,3680.92 ccw(c4267.14,3680.92) U1.11@4233.81,3647.59 ; U1.11@4220,3657.66 U1.11 4220,3695 4325,3800 4347.34,3800 4375,3827.66 4375,3965 4535,4125 4535,4270 4725,4460 ge.6 ; 4688.13,4423.13 ccw(c4646.26,4465) ge.6@4705.47,4465 ; 4700.2,4435.2 cw(c4725,4410.4) ge.6@4725,4445.47
SHI3: ge.4 U1.10 | length 866.2
  Bottom Layer w20: U1.10@4319.64,3606.52 ccw(c4341.29,3588.53) 4321.38,3568.62 ; U1.10 4320,3570 ; U1.10@4335.02,3593.74 ccw(c4358.23,3574.45) 4336.89,3553.11 ; ge.4@4605.47,3865 cw(c4558.33,3865) 4591.66,3831.66 cw(c4625,3798.33) ge.4@4625,3845.47 ; ge.4 4560,3800 4510,3800 4500.47,3790.47 4500.47,3725.47 4470.47,3695.47 4470.47,3580.47 4425,3535 4355,3535 4320,3570 ; 4320,3570 ccw(c4296.18,3570) 4309.27,3589.91 cw(c4296.18,3570) 4320,3570 ; 4320,3570 cw(c4343.82,3570) 4330.73,3589.91 ccw(c4343.82,3570) 4320,3570
SHI4: ge.2 U1.9 | length 512
  Bottom Layer w20: U1.9@4406.19,3647.59 ccw(c4372.86,3680.92) 4420,3680.92 ccw(c4467.14,3680.92) U1.9@4433.81,3647.59 ; ge.2@4411.19,3851.19 cw(c4317.5,3757.5) 4450,3757.5 ; U1.9 4420,3715 4450,3745 4450,3840 ge.2 ; ge.2@4425.33,3865.33 cw(c4365.79,3805.79) 4450,3805.79
SHI5: ge.1 pad.2 pad.3 U1.14 | length 1593.8
  Top Layer w30: pad.2 4335,4035 pad.3 ; pad.2@4152.68,4017.32 cw(c4195.36,3974.64) 4195.36,4035 cw(c4195.36,4095.36) pad.2@4152.68,4052.68 ; 4267.57,4035 cw(c4267.57,3957.57) pad.3@4322.32,4012.32 ; 4291.72,4035 ccw(c4291.72,4078.28) pad.3@4322.32,4047.68
  Bottom Layer w20: U1.14@3906.19,3647.59 ccw(c3872.86,3680.92) 3920,3680.92 ccw(c3967.14,3680.92) U1.14@3933.81,3647.59 ; U1.14 3920,3709.96 4054.53,3844.49 4054.53,4004.53 ; 4081.14,4004.53 ccw(c4081.14,4050.6) pad.2@4125.39,4037.78 ; pad.2@4106.18,4043.35 cw(c4054.53,4058.3) 4054.53,4004.53 ; 4107.76,4004.53 ccw(c4107.76,4042.89) pad.2@4144.61,4032.22 ; pad.2 4104.53,4004.53 4054.53,4004.53 ; pad.3@4310,4040 4325,4025 ge.1 ; ge.1@4311.19,3878.81 ccw(c4277.86,3912.14) 4325,3912.14 ccw(c4372.14,3912.14) ge.1@4338.81,3878.81 ; 4325,3921.36 cw(c4448.64,3921.36) pad.3@4361.21,4008.79 ; 4325,3969.64 cw(c4400.36,3969.64) pad.3@4347.07,4022.93
SHI6: ge.9 U1.13 | length 1350.2
  Bottom Layer w20: U1.13@4006.19,3647.59 ccw(c3972.86,3680.92) 4020,3680.92 ccw(c4067.14,3680.92) U1.13@4033.81,3647.59 ; U1.13@4030,3630 U1.13 4020,3685 4154.53,3819.53 4154.53,3889.53 4205,3940 4205,4350 4265,4410 4265,4505 4295,4535 4355,4535 ge.9 ; ge.9@4405.47,4465 ccw(c4358.33,4465) 4391.66,4498.34 ccw(c4425,4531.67) ge.9@4425,4484.53
SHI7: ge.10 U1.25 | length 1861.3
  Bottom Layer w20: U1.25@3706.19,3047.59 ccw(c3672.86,3080.92) 3720,3080.92 ccw(c3767.14,3080.92) U1.25@3733.81,3047.59 ; U1.25 3720,3195 4070.47,3545.47 4070.47,3680.47 4185,3795 4215,3795 4242.72,3822.72 4242.72,4247.72 4325,4330 ge.10 ; ge.10@4311.19,4451.19 cw(c4277.86,4417.86) 4325,4417.86 cw(c4372.14,4417.86) ge.10@4338.81,4451.19
VCC: POWER.3 POWER.4 R1.2 R2.2 R3.2 R4.2 R5.2 U1.1 | length 8241.3
  Bottom Layer w20: POWER.4@3606.19,2387.59 ccw(c3572.86,2420.92) 3620,2420.92 ccw(c3667.14,2420.92) POWER.4@3633.81,2387.59 ; POWER.3@3606.19,2432.41 cw(c3572.86,2399.08) 3620,2399.08 cw(c3667.14,2399.08) POWER.3@3633.81,2432.41 ; POWER.4@3620,2326.69 cw(c3620,2246.28) 3676.86,2303.14 ; POWER.3 POWER.4 3690,2290 5250,2290 5311.5,2351.5 5311.5,3620 ; R1.2 3650,4605 3705,4660 4665,4660 ; R1.2@3650,4621.5 ccw(c3650,4661.32) 3678.16,4633.16 ; R1.2@3671.5,4600 cw(c3735.46,4600) 3690.23,4645.23 ; R2.2@4135.21,4615.6 ccw(c4102.6,4650) 4150,4650 ; 4145,4655 4150,4650 ; R2.2 4150,4650 ; R2.2@4164.79,4615.6 cw(c4197.4,4650) 4150,4650 ; R3.2@4654.8,4615.2 ccw(c4618.1,4651.9) 4670,4651.9 ccw(c4721.9,4651.9) R3.2@4685.2,4615.2 ; R3.2 4670,4655 4665,4660 ; R5.2@4981.5,2590 cw(c5033.39,2590) 4996.7,2626.7 ; R5.2@4988.14,2607.93 ccw(c4973.53,2630) 5000,2630 ; R5.2 5000,2630 ; R5.2@5001.5,2590 cw(c5101.68,2590) 5030.84,2660.84 ; R5.2@5011.86,2607.93 cw(c5026.47,2630) 5000,2630 ; R5.2@5021.5,2590 cw(c5169.96,2590) 5064.98,2694.98 ; R4.2@5174.8,4615.2 ccw(c5138.1,4651.9) 5190,4651.9 ccw(c5241.9,4651.9) R4.2@5205.2,4615.2 ; R4.2 5190,4660 ; U1.1@5206.19,3592.41 cw(c5172.86,3559.08) 5220,3559.08 cw(c5267.14,3559.08) U1.1@5233.81,3592.41 ; U1.1@5233.81,3606.19 cw(c5267.14,3572.86) 5267.14,3620 cw(c5267.14,3667.14) U1.1@5233.81,3633.81 ; 4665,4660 5190,4660 ; 5000,2630 5144.95,2774.95 5157.78,2774.95 5251.5,2868.67 5251.5,2911.33 5206.13,2956.69 5199.49,2956.69 5170.47,2985.71 5170.47,3425.47 5220,3475 U1.1 5311.5,3620 ; 5190,4660 5240,4660 5311.5,4588.5 5311.5,3620
pads on no net: bai.3 bai.5 ge.3 qian.1 qian.2 qian.3 qian.5 qian.7 qian.9 shi.3 shi.5 U1.37

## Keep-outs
Keep-Out Layer:
  lines w20: 3115,4710 3120,4715 ; 5390,4700 5390,4735 3115,4735 3115,2185 5390,2185 5390,4715

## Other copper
Bottom Layer:
  text "数字电压电流表" at 5105,3285 h150
  text "-5" at 3410,2200 h100
  text "GND" at 3600,2200 h100
  text "+5" at 3720,2200 h100
  text "-" at 5195,2200 h150
  text "+" at 5000,2195 h150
